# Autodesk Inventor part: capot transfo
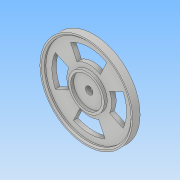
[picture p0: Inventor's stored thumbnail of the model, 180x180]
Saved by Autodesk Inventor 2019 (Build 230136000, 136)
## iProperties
Created: 2024-09
Part Number: capot transfo
Material: Générique
Document SubType Name: Modeling
Designer: admin
Density: 1 g/cm^3
Appearance: Par défaut
Author: admin
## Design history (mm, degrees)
sketch "Esquisse1"
  geometry: C1 r 31 at (0, 0); C2 r 2.5 at (0, 0); 1 further point
  constraints: 2 centre point, 2 coincident
  dimensions: "d0" = 62 diameter of C1; "d1" = 5 diameter of C2
extrude "Extrusion1" new body sketch "Esquisse1" distance "d2" = 3; taper "d3" = 0 deg
sketch "Esquisse2"
  geometry: C1 r 10.4 at (0, 0); C2 r 12 at (0, 0); C3 r 29 at (0, 0); C4 r 31 at (0, 0) reference; 1 further point
  constraints: 3 centre point, 3 coincident
  dimensions: "d4" = 20.8 diameter of C1; "d5" = 24 diameter of C2; "d6" = 58 diameter of C3
extrude "Extrusion2" join sketch "Esquisse2" distance "d7" = 2; taper "d8" = 0 deg
chamfer "Chanfrein1" distance "d9" = 1; stored, may be unused: second distance "d10" = 2, angle "d11" = 45 deg
sketch "Esquisse3" dims "d13" = 30
  geometry: L1 (7.5, 12.99)-(11.736, 22.074); L2 (-8.247, 12.53)-(-12.5, 21.651); L3 (0, 0)-(0, 15); L4 (-6.339, -13.595)-(-10.565, -22.658); L5 (6.339, -13.595)-(10.565, -22.658); L6 (0, 0)-(0, -15); L7 (-13.595, 6.339)-(-22.658, 10.565); L8 (-13.595, -6.339)-(-22.658, -10.565); L9 (0, 0)-(-15, 0); L10 (13.595, -6.339)-(22.658, -10.565); L11 (13.595, 6.339)-(22.658, 10.565); A1 r 25 centre (0, 0) between (-22.658, 10.565) and (-22.658, -10.565); A2 r 25 centre (0, 0) between (-10.565, -22.658) and (10.565, -22.658); A3 r 25 centre (0, 0) between (22.658, -10.565) and (22.658, 10.565); A4 r 25 centre (0, 0) between (11.736, 22.074) and (-12.5, 21.651); 2 further points
  constraints: 22 end point, 8 point on circle, 4 centre point, 2 coincident, 2 vertical, 1 horizontal, 13 other
  dimensions: "d14" = 25 deg angle of L3 L2; "d15" = 25 deg angle of L1 L3; "d16" = 25 deg angle of L6 L4; "d17" = 25 deg angle of L5 L6; "d18" = 25 deg angle of L9 L8; "d19" = 25 deg angle of L9 L7
extrude "Extrusion3" cut sketch "Esquisse3" distance "d22" = 10; taper "d23" = 0 deg
node "Solide1"
